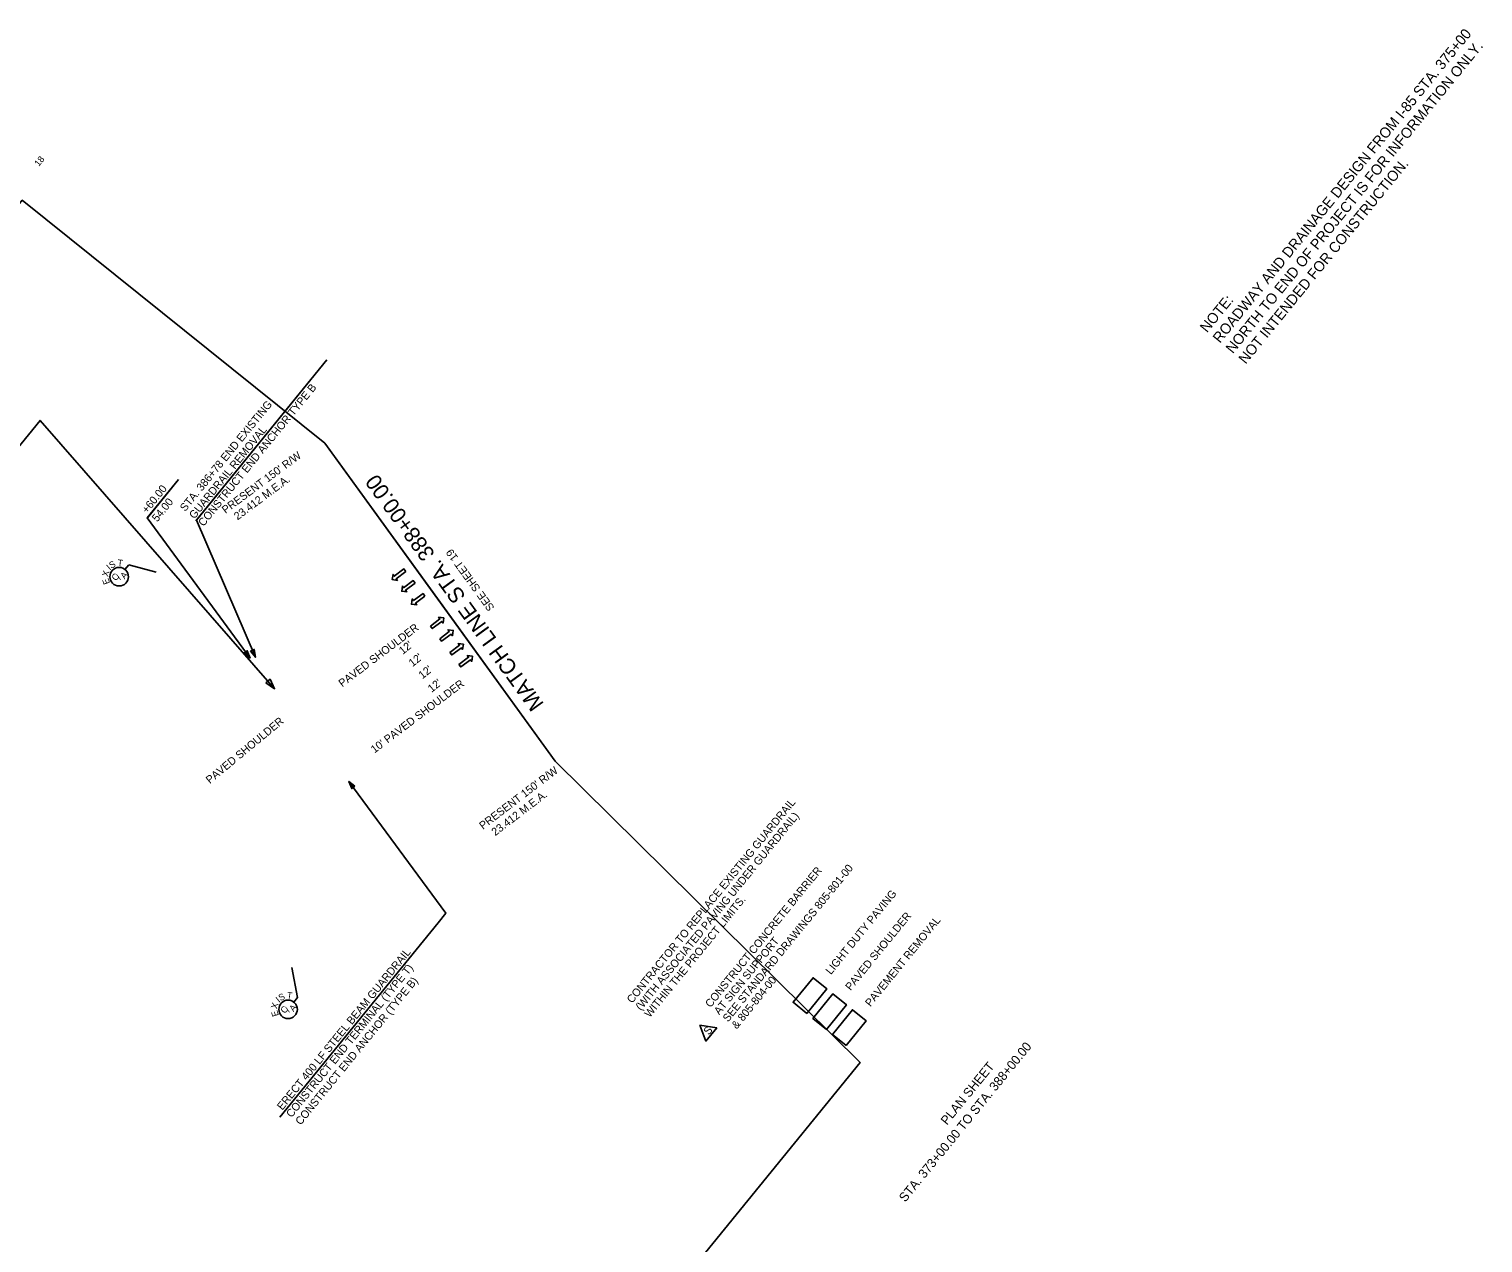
# Model space of a CAD drawing. Extents: x 1615766 to 1617965, y 1099429 to 1101416.
# Drawn here: x 1616854 to 1617965, y 1100488 to 1101416 of the extents above; entities that cross this region are included whole.
import ezdxf

# ---------------------------------------------------------------- set-up
doc = ezdxf.new("R2010")
doc.units = 0
for name, color, linetype in [('RD_EX_Bldg', 7, 'Continuous'), ('RD_EX_Conc', 7, 'Continuous'), ('RD_EX_Driveway', 7, 'Continuous'), ('RD_EX_DV_TX_Gov', 7, 'Continuous'), ('RD_EX_Fence_ChLk', 7, 'Continuous'), ('RD_EX_H2O_WetLd', 7, 'Continuous'), ('RD_EX_Misc_Golf_Teebox', 7, 'Continuous'), ('RD_EX_VEG', 7, 'Continuous')]:
    doc.layers.add(name, color=color, linetype=linetype)

msp = doc.modelspace()

# ---------------------------------------------------------------- linework, layer by layer
at = {"layer": 'RD_EX_Bldg'}
for points in [[(1617142, 1101001), (1617140.6, 1101002.9), (1617133.2, 1100997.4), (1617132.3, 1100998.7), (1617131.7, 1100994.8), (1617135.7, 1100994.2), (1617134.7, 1100995.5)], [(1617149.2, 1100992.1), (1617147.8, 1100994.1), (1617140.4, 1100988.6), (1617139.4, 1100989.9), (1617138.9, 1100985.9), (1617142.8, 1100985.4), (1617141.8, 1100986.7)], [(1617156.7, 1100982.2), (1617155.3, 1100984.1), (1617148, 1100978.7), (1617147, 1100980), (1617146.4, 1100976), (1617150.4, 1100975.4), (1617149.4, 1100976.7)], [(1617160.8, 1100959.2), (1617162.2, 1100957.3), (1617169.5, 1100962.8), (1617170.5, 1100961.5), (1617171.1, 1100965.5), (1617167.1, 1100966), (1617168.1, 1100964.7)], [(1617168, 1100949.6), (1617169.4, 1100947.7), (1617176.7, 1100953.2), (1617177.7, 1100951.9), (1617178.3, 1100955.9), (1617174.3, 1100956.5), (1617175.3, 1100955.2)], [(1617175.7, 1100939.2), (1617177.2, 1100937.2), (1617184.5, 1100942.7), (1617185.5, 1100941.4), (1617186.1, 1100945.4), (1617182.1, 1100946), (1617183.1, 1100944.7)], [(1617182.6, 1100930), (1617184.1, 1100928), (1617191.4, 1100933.5), (1617192.4, 1100932.2), (1617193, 1100936.2), (1617189, 1100936.7), (1617190, 1100935.4)]]:
    msp.add_lwpolyline(points, close=True, dxfattribs=at)
at = {"layer": 'RD_EX_Driveway'}
for p, q in [((1617081.8, 1101162.7), (1616981.7, 1101039.7)), ((1617166.7, 1100732.5), (1617045.7, 1100583.9))]:
    msp.add_line(p, q, dxfattribs=at)
for points in [[(1617081.8, 1101162.7), (1616982.1, 1101040.2), (1617027.1, 1100935.4)], [(1617166.7, 1100732.5), (1617172.6, 1100739.8), (1617098.6, 1100840.6)]]:
    msp.add_lwpolyline(points, dxfattribs=at)
for points in [[(1617023.4, 1100940.1), (1617027.1, 1100935.4), (1617026.2, 1100941.4)], [(1617103.2, 1100836.8), (1617098.6, 1100840.6), (1617100.7, 1100835)]]:
    msp.add_lwpolyline(points, close=True, dxfattribs=at)
at = {"layer": 'RD_EX_DV_TX_Gov'}
for p, q in [((1616927.4, 1101002.5), (1616930.3, 1101006.1)), ((1616930.3, 1101006.1), (1616951.4, 1101000.4)), ((1617059.4, 1100675.4), (1617055, 1100698.2)), ((1617056.5, 1100671.8), (1617059.4, 1100675.4))]:
    msp.add_line(p, q, dxfattribs=at)
for centre in [(1616923, 1100997), (1617052.1, 1100666.3)]:
    msp.add_circle(centre, 7.08, dxfattribs=at)
at = {"layer": 'RD_EX_Fence_ChLk'}
msp.add_lwpolyline([(1616368.7, 1099765.8), (1616621.6, 1099560), (1617489.2, 1100625.8), (1617256.2, 1100856.1), (1617080.1, 1101099), (1616848.9, 1101284.7), (1616739.1, 1101147.9), (1616711.3, 1101170.2), (1615865, 1100129.8), (1615884.6, 1100113.8), (1615821.9, 1100036.8), (1616095.1, 1099888.9)], close=True, dxfattribs=at)
msp.add_lwpolyline([(1616368.7, 1099765.8), (1616621.6, 1099560), (1617489.2, 1100625.8), (1617256.2, 1100856.1), (1617080.1, 1101099), (1616848.9, 1101284.7), (1616739.1, 1101147.9), (1616711.3, 1101170.2), (1615865, 1100129.8), (1615884.6, 1100113.8), (1615821.9, 1100036.8), (1616095.1, 1099888.9)], close=True, dxfattribs=at)
at = {"layer": 'RD_EX_Misc_Golf_Teebox'}
msp.add_line((1616968.4, 1101071.3), (1616944.6, 1101042), dxfattribs=at)
for points in [[(1616670.4, 1100880.5), (1616862.6, 1101116.5), (1617041.8, 1100911.4)], [(1616968.4, 1101071.3), (1616944.5, 1101041.9), (1617023.1, 1100934.8)], [(1617448.4, 1100663.2), (1617463.7, 1100682), (1617453.3, 1100690.5), (1617438, 1100671.7), (1617448.4, 1100663.2)], [(1617463.5, 1100651), (1617478.8, 1100669.8), (1617468.4, 1100678.3), (1617453.1, 1100659.4), (1617463.5, 1100651)], [(1617478.6, 1100638.7), (1617493.9, 1100657.5), (1617483.4, 1100666), (1617468.1, 1100647.2), (1617478.6, 1100638.7)]]:
    msp.add_lwpolyline(points, dxfattribs=at)
for points in [[(1617018.4, 1100938.6), (1617023.1, 1100934.8), (1617020.9, 1100940.4)], [(1617035.2, 1100915.9), (1617041.8, 1100911.4), (1617038.3, 1100918.6)], [(1617448.4, 1100663.2), (1617463.7, 1100682), (1617453.3, 1100690.5), (1617438, 1100671.7)], [(1617463.5, 1100651), (1617478.8, 1100669.8), (1617468.4, 1100678.3), (1617453.1, 1100659.4)], [(1617478.6, 1100638.7), (1617493.9, 1100657.5), (1617483.4, 1100666), (1617468.1, 1100647.2)], [(1617366.8, 1100654.2), (1617371.4, 1100642), (1617379.7, 1100652.1)]]:
    msp.add_lwpolyline(points, close=True, dxfattribs=at)
at = {"layer": 'RD_EX_VEG'}
msp.add_lwpolyline([(1617256.2, 1100856.1), (1617168.2, 1100977.6), (1617080.1, 1101099)], dxfattribs=at)

# ---------------------------------------------------------------- texts
at = {"layer": 'RD_EX_Conc'}
for s, rotation, p in [("PRESENT 150' R/W ", 36.685, (1617004.3, 1101044.9)), ('  23.412 M.E.A.', 36.685, (1617009.9, 1101037.3)), ("PRESENT 150' R/W ", 37.34, (1617201, 1100803.5)), ('  23.412 M.E.A.', 37.34, (1617206.8, 1100795.9))]:
    msp.add_text(s, height=6, rotation=rotation, dxfattribs=at).set_placement(p)
at = {"layer": 'RD_EX_Driveway'}
for s, p in [('CONSTRUCT END ANCHOR TYPE B', (1616987.5, 1101035)), ('STA. 386+78 END EXISTING', (1616973.5, 1101046.4)), ('GUARDRAIL REMOVAL', (1616980.5, 1101040.7)), ('ERECT 400 LF STEEL BEAM GUARDRAIL', (1617047.7, 1100588.8)), ('CONSTRUCT END TERMINAL (TYPE T)', (1617054.7, 1100583.1)), ('CONSTRUCT END ANCHOR (TYPE B)', (1617061.7, 1100577.4))]:
    msp.add_text(s, height=6, rotation=50.8545, dxfattribs=at).set_placement(p)
at = {"layer": 'RD_EX_DV_TX_Gov'}
for s, rotation, p in [('S', 29.0661, (1616917, 1101003)), ('T', 353.9046, (1616921.5, 1101005.3)), ('X', 75.948, (1616914.5, 1100996.7)), ('I', 40.7866, (1616915.9, 1101001.6)), ('C', 50.8513, (1616920.5, 1100993.4)), ('/', 50.8513, (1616924, 1100994.4)), ('A', 50.8513, (1616927.2, 1100994.8)), ('E', 109.4352, (1616916.1, 1100992.1)), ('I', 38.8344, (1617045.1, 1100671.2)), ('S', 27.1139, (1617046.3, 1100672.5)), ('T', 351.9524, (1617050.9, 1100674.7)), ('X', 73.9959, (1617043.6, 1100666.3)), ('E', 107.483, (1617045.1, 1100661.7)), ('C', 50.8513, (1617049.6, 1100662.7)), ('/', 50.8513, (1617053.1, 1100663.7)), ('A', 50.8513, (1617056.3, 1100664.1))]:
    msp.add_text(s, height=5, rotation=rotation, dxfattribs=at).set_placement(p)
at = {"layer": 'RD_EX_H2O_WetLd'}
for s, height, p in [('STA. 373+00.00 TO STA. 388+00.00', 6.983, (1617523.7, 1100518.5)), ('PLAN SHEET', 6.98, (1617555.6, 1100577.4))]:
    msp.add_text(s, height=height, rotation=50.8545, dxfattribs=at).set_placement(p)
at = {"layer": 'RD_EX_Misc_Golf_Teebox'}
for s, height, rotation, p in [('18', 5, 50.8545, (1616861.6, 1101310.2)), ('+60.00', 6, 50.8545, (1616944.3, 1101044.9)), ('54.00', 6, 50.8545, (1616952.1, 1101038.5)), (' PAVED SHOULDER', 6, 37.0677, (1617091.7, 1100911)), ("12'", 6, 38.6259, (1617139.7, 1100937.2)), ("12'", 6, 38.6259, (1617147.2, 1100927.8)), ("12'", 6, 38.6259, (1617154.7, 1100918.5)), ("12'", 6, 38.6259, (1617161.8, 1100908.2)), ("10' PAVED SHOULDER", 6, 37.0677, (1617118.1, 1100861.8)), (' PAVED SHOULDER', 6, 39.6691, (1616990.6, 1100837)), ('CONTRACTOR TO REPLACE EXISTING GUARDRAIL', 6, 50.8545, (1617315, 1100670.5)), ('(WITH ASSOCIATED PAVING UNDER GUARDRAIL)', 6, 50.8545, (1617321.7, 1100665)), ('CONSTRUCT CONCRETE BARRIER ', 6, 50.8545, (1617374.9, 1100667.2)), ('SEE STANDARD DRAWINGS 805-801-00', 6, 50.8545, (1617388.3, 1100656.2)), ('LIGHT DUTY PAVING', 6, 50.8545, (1617466.9, 1100692.4)), ('WITHIN THE PROJECT LIMITS.', 6, 50.8545, (1617328.5, 1100659.6)), ('PAVED SHOULDER', 6, 50.8545, (1617482, 1100680.2)), ('PAVEMENT REMOVAL', 6, 50.8545, (1617497.1, 1100667.9)), ('AT SIGN SUPPORT', 6, 50.8545, (1617381.6, 1100661.7)), ('& 805-804-00', 6, 50.8545, (1617395, 1100650.8)), ('S', 6, 50.8545, (1617373.6, 1100646.2))]:
    msp.add_text(s, height=height, rotation=rotation, dxfattribs=at).set_placement(p)
at = {"layer": 'RD_EX_VEG'}
for s, height, rotation, p in [('ROADWAY AND DRAINAGE DESIGN FROM I-85 STA. 375+00', 8, 50.8545, (1617764.2, 1101175)), ('NORTH TO END OF PROJECT IS FOR INFORMATION ONLY.', 8, 50.8545, (1617774.1, 1101167)), ('NOT INTENDED FOR CONSTRUCTION.', 8, 50.8545, (1617783.9, 1101159)), ('NOTE:', 8, 50.8545, (1617754.4, 1101183)), ('MATCH LINE STA. 388+00.00', 12, 125.9354, (1617248, 1100899.8)), ('SEE SHEET 19', 6, 125.9354, (1617210.1, 1100973.4))]:
    msp.add_text(s, height=height, rotation=rotation, dxfattribs=at).set_placement(p)

doc.saveas('drawing.dxf')
